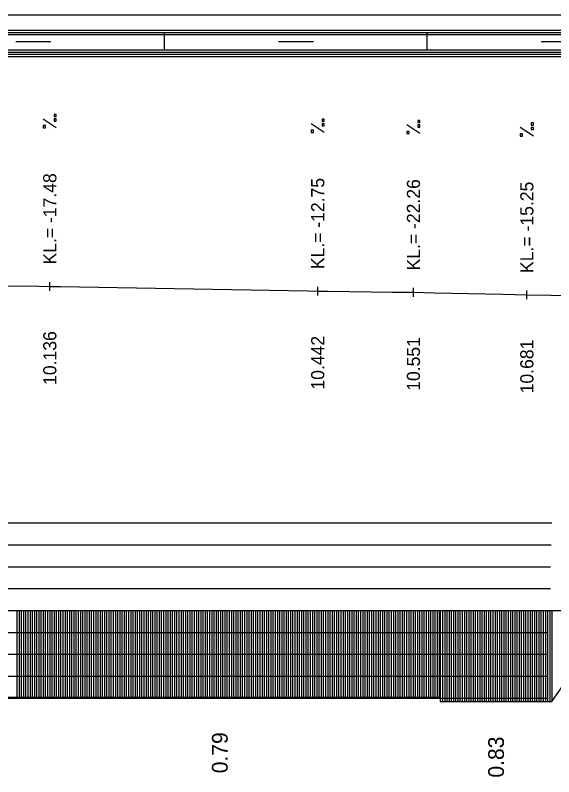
# Model space of a CAD drawing. Extents: x 2 to 10148, y 0 to 380.
# Drawn here: x 1307.9 to 1369.4, y 293 to 380 of the extents above; entities that cross this region are included whole.
import ezdxf

# ---------------------------------------------------------------- set-up
doc = ezdxf.new("R2010")
doc.units = 0
for name, color, linetype in [('NIVELETA_CARA', 7, 'Continuous'), ('NIVELETA_TEXT', 7, 'Continuous'), ('RAM', 7, 'Continuous'), ('ZRYCHL_CARA_C', 7, 'Continuous'), ('ZRYCHL_RASTR', 7, 'Continuous'), ('ZRYCHL_TEXT', 7, 'Continuous')]:
    doc.layers.add(name, color=color, linetype=linetype)

msp = doc.modelspace()

# ---------------------------------------------------------------- linework, layer by layer
at = {"layer": 'NIVELETA_CARA'}
for p, q in [((1306.124, 349.095), (1310.651, 349.038)), ((1310.651, 349.038), (1311.883, 349.022)), ((1311.883, 348.522), (1311.883, 349.522)), ((1311.883, 349.022), (1313.114, 349.001)), ((1313.114, 349.001), (1341.305, 348.508)), ((1342.487, 347.987), (1342.487, 348.987)), ((1353.419, 347.848), (1353.419, 348.848)), ((1341.305, 348.508), (1342.487, 348.487)), ((1342.487, 348.487), (1343.669, 348.472)), ((1343.669, 348.472), (1351.044, 348.378)), ((1351.044, 348.378), (1353.419, 348.348)), ((1353.419, 348.348), (1355.795, 348.295)), ((1355.795, 348.295), (1363.64, 348.12)), ((1363.64, 348.12), (1366.373, 348.06)), ((1366.373, 347.56), (1366.373, 348.56)), ((1366.373, 348.06), (1369.105, 348.018)), ((1369.105, 348.018), (1381.569, 347.828))]:
    msp.add_line(p, q, dxfattribs=at)
at = {"layer": 'NIVELETA_TEXT'}
for p, q in [((1312.63, 367.149), (1311.136, 368.14)), ((1312.631, 368.666), (1312.383, 368.666)), ((1312.383, 368.666), (1312.383, 368.423)), ((1312.383, 368.423), (1312.388, 368.418)), ((1312.383, 368.418), (1312.631, 368.418)), ((1312.631, 368.154), (1312.383, 368.154)), ((1312.383, 368.154), (1312.383, 367.911)), ((1312.631, 368.418), (1312.631, 368.666)), ((1312.631, 367.907), (1312.631, 368.154)), ((1343.235, 368.131), (1342.987, 368.131)), ((1342.987, 368.131), (1342.987, 367.888)), ((1343.235, 367.883), (1343.235, 368.131)), ((1354.167, 367.991), (1353.92, 367.991)), ((1353.92, 367.991), (1353.92, 367.748)), ((1354.167, 367.744), (1354.167, 367.991)), ((1311.383, 367.397), (1311.136, 367.397)), ((1311.136, 367.397), (1311.136, 367.154)), ((1311.136, 367.154), (1311.14, 367.149)), ((1311.136, 367.149), (1311.383, 367.149)), ((1311.383, 367.149), (1311.383, 367.397)), ((1312.383, 367.911), (1312.388, 367.907)), ((1312.383, 367.907), (1312.631, 367.907)), ((1343.234, 366.614), (1341.74, 367.605)), ((1342.987, 367.888), (1342.992, 367.883)), ((1342.987, 367.883), (1343.235, 367.883)), ((1343.235, 367.619), (1342.987, 367.619)), ((1342.987, 367.619), (1342.987, 367.376)), ((1342.987, 367.376), (1342.992, 367.372)), ((1342.987, 367.372), (1343.235, 367.372)), ((1343.235, 367.372), (1343.235, 367.619)), ((1354.166, 366.475), (1352.672, 367.466)), ((1353.92, 367.748), (1353.925, 367.744)), ((1353.92, 367.744), (1354.167, 367.744)), ((1354.167, 367.48), (1353.92, 367.48)), ((1353.92, 367.48), (1353.92, 367.237)), ((1353.92, 367.237), (1353.925, 367.232)), ((1353.92, 367.232), (1354.167, 367.232)), ((1354.167, 367.232), (1354.167, 367.48)), ((1367.119, 366.187), (1365.625, 367.177)), ((1367.12, 367.703), (1366.873, 367.703)), ((1366.873, 367.703), (1366.873, 367.46)), ((1366.873, 367.46), (1366.878, 367.455)), ((1366.873, 367.455), (1367.12, 367.455)), ((1367.12, 367.192), (1366.873, 367.192)), ((1366.873, 367.192), (1366.873, 366.949)), ((1367.12, 367.455), (1367.12, 367.703)), ((1367.12, 366.944), (1367.12, 367.192)), ((1341.987, 366.862), (1341.74, 366.862)), ((1341.74, 366.862), (1341.74, 366.619)), ((1341.74, 366.619), (1341.745, 366.614)), ((1341.74, 366.614), (1341.987, 366.614)), ((1341.987, 366.614), (1341.987, 366.862)), ((1352.92, 366.723), (1352.672, 366.723)), ((1352.672, 366.723), (1352.672, 366.48)), ((1352.672, 366.48), (1352.677, 366.475)), ((1352.672, 366.475), (1352.92, 366.475)), ((1352.92, 366.475), (1352.92, 366.723)), ((1365.873, 366.434), (1365.625, 366.434)), ((1365.625, 366.434), (1365.625, 366.191)), ((1365.873, 366.187), (1365.873, 366.434)), ((1366.873, 366.949), (1366.878, 366.944)), ((1366.873, 366.944), (1367.12, 366.944)), ((1365.625, 366.191), (1365.63, 366.187)), ((1365.625, 366.187), (1365.873, 366.187))]:
    msp.add_line(p, q, dxfattribs=at)
at = {"layer": 'RAM'}
for p, q in [((1850.829, 380), (1245.39, 380)), ((1850.829, 378.25), (1245.39, 378.25)), ((1850.829, 378), (1245.39, 378)), ((1850.829, 377.75), (1245.39, 377.75)), ((1325, 376), (1325, 378)), ((1355, 376), (1355, 378)), ((1308, 377), (1312, 377)), ((1338, 377), (1342, 377)), ((1368, 377), (1372, 377)), ((1850.829, 376), (1245.39, 376)), ((1850.829, 375.75), (1245.39, 375.75)), ((1850.829, 375.5), (1245.39, 375.5)), ((1850.829, 375.25), (1245.39, 375.25))]:
    msp.add_line(p, q, dxfattribs=at)
at = {"layer": 'ZRYCHL_CARA_C'}
for p, q in [((1245.39, 312), (1850.829, 312)), ((1308.124, 312), (1308.124, 302.112)), ((1308.374, 312), (1308.374, 302.112)), ((1308.624, 312), (1308.624, 302.112)), ((1308.874, 312), (1308.874, 302.112)), ((1309.124, 312), (1309.124, 302.112)), ((1309.374, 312), (1309.374, 302.112)), ((1309.624, 312), (1309.624, 302.112)), ((1309.874, 312), (1309.874, 302.112)), ((1310.124, 312), (1310.124, 302.112)), ((1310.374, 312), (1310.374, 302.112)), ((1310.624, 312), (1310.624, 302.112)), ((1310.874, 312), (1310.874, 302.112)), ((1311.124, 312), (1311.124, 302.112)), ((1311.374, 312), (1311.374, 302.112)), ((1311.624, 312), (1311.624, 302.112)), ((1311.874, 312), (1311.874, 302.112)), ((1312.124, 312), (1312.124, 302.112)), ((1312.374, 312), (1312.374, 302.112)), ((1312.624, 312), (1312.624, 302.112)), ((1312.874, 312), (1312.874, 302.112)), ((1313.124, 312), (1313.124, 302.112)), ((1313.374, 312), (1313.374, 302.112)), ((1313.624, 312), (1313.624, 302.112)), ((1313.874, 312), (1313.874, 302.112)), ((1314.124, 312), (1314.124, 302.112)), ((1314.374, 312), (1314.374, 302.112)), ((1314.624, 312), (1314.624, 302.112)), ((1314.874, 312), (1314.874, 302.112)), ((1315.124, 312), (1315.124, 302.112)), ((1315.374, 312), (1315.374, 302.112)), ((1315.624, 312), (1315.624, 302.112)), ((1315.874, 312), (1315.874, 302.112)), ((1316.124, 312), (1316.124, 302.112)), ((1316.374, 312), (1316.374, 302.112)), ((1316.624, 312), (1316.624, 302.112)), ((1316.874, 312), (1316.874, 302.112)), ((1317.124, 312), (1317.124, 302.112)), ((1317.374, 312), (1317.374, 302.112)), ((1317.624, 312), (1317.624, 302.112)), ((1317.874, 312), (1317.874, 302.112)), ((1318.124, 312), (1318.124, 302.112)), ((1318.374, 312), (1318.374, 302.112)), ((1318.624, 312), (1318.624, 302.112)), ((1318.874, 312), (1318.874, 302.112)), ((1319.124, 312), (1319.124, 302.112)), ((1319.374, 312), (1319.374, 302.112)), ((1319.624, 312), (1319.624, 302.112)), ((1319.874, 312), (1319.874, 302.112)), ((1320.124, 312), (1320.124, 302.112)), ((1320.374, 312), (1320.374, 302.112)), ((1320.624, 312), (1320.624, 302.112)), ((1320.874, 312), (1320.874, 302.112)), ((1321.124, 312), (1321.124, 302.112)), ((1321.374, 312), (1321.374, 302.112)), ((1321.624, 312), (1321.624, 302.112)), ((1321.874, 312), (1321.874, 302.112)), ((1322.124, 312), (1322.124, 302.112)), ((1322.374, 312), (1322.374, 302.112)), ((1322.624, 312), (1322.624, 302.112)), ((1322.874, 312), (1322.874, 302.112)), ((1323.124, 312), (1323.124, 302.112)), ((1323.374, 312), (1323.374, 302.112)), ((1323.624, 312), (1323.624, 302.112)), ((1323.874, 312), (1323.874, 302.112)), ((1324.124, 312), (1324.124, 302.112)), ((1324.374, 312), (1324.374, 302.112)), ((1324.624, 312), (1324.624, 302.112)), ((1324.874, 312), (1324.874, 302.112)), ((1325.124, 312), (1325.124, 302.112)), ((1325.374, 312), (1325.374, 302.112)), ((1325.624, 312), (1325.624, 302.112)), ((1325.874, 312), (1325.874, 302.112)), ((1326.124, 312), (1326.124, 302.112)), ((1326.374, 312), (1326.374, 302.112)), ((1326.624, 312), (1326.624, 302.112)), ((1326.874, 312), (1326.874, 302.112)), ((1327.124, 312), (1327.124, 302.112)), ((1327.374, 312), (1327.374, 302.112)), ((1327.624, 312), (1327.624, 302.112)), ((1327.874, 312), (1327.874, 302.112)), ((1328.124, 312), (1328.124, 302.112)), ((1328.374, 312), (1328.374, 302.112)), ((1328.624, 312), (1328.624, 302.112)), ((1328.874, 312), (1328.874, 302.112)), ((1329.124, 312), (1329.124, 302.112)), ((1329.374, 312), (1329.374, 302.112)), ((1329.624, 312), (1329.624, 302.112)), ((1329.874, 312), (1329.874, 302.112)), ((1330.124, 312), (1330.124, 302.112)), ((1330.374, 312), (1330.374, 302.112)), ((1330.624, 312), (1330.624, 302.112)), ((1330.874, 312), (1330.874, 302.112)), ((1331.124, 312), (1331.124, 302.112)), ((1331.374, 312), (1331.374, 302.112)), ((1331.624, 312), (1331.624, 302.112)), ((1331.874, 312), (1331.874, 302.112)), ((1332.124, 312), (1332.124, 302.112)), ((1332.374, 312), (1332.374, 302.112)), ((1332.624, 312), (1332.624, 302.112)), ((1332.874, 312), (1332.874, 302.112)), ((1333.124, 312), (1333.124, 302.112)), ((1333.374, 312), (1333.374, 302.112)), ((1333.624, 312), (1333.624, 302.112)), ((1333.874, 312), (1333.874, 302.112)), ((1334.124, 312), (1334.124, 302.112)), ((1334.374, 312), (1334.374, 302.112)), ((1334.624, 312), (1334.624, 302.112)), ((1334.874, 312), (1334.874, 302.112)), ((1335.124, 312), (1335.124, 302.112)), ((1335.374, 312), (1335.374, 302.112)), ((1335.624, 312), (1335.624, 302.112)), ((1335.874, 312), (1335.874, 302.112)), ((1336.124, 312), (1336.124, 302.112)), ((1336.374, 312), (1336.374, 302.112)), ((1336.624, 312), (1336.624, 302.112)), ((1336.874, 312), (1336.874, 302.112)), ((1337.124, 312), (1337.124, 302.112)), ((1337.374, 312), (1337.374, 302.112)), ((1337.624, 312), (1337.624, 302.112)), ((1337.874, 312), (1337.874, 302.112)), ((1338.124, 312), (1338.124, 302.112)), ((1338.374, 312), (1338.374, 302.112)), ((1338.624, 312), (1338.624, 302.112)), ((1338.874, 312), (1338.874, 302.112)), ((1339.124, 312), (1339.124, 302.112)), ((1339.374, 312), (1339.374, 302.112)), ((1339.624, 312), (1339.624, 302.112)), ((1339.874, 312), (1339.874, 302.112)), ((1340.124, 312), (1340.124, 302.112)), ((1340.374, 312), (1340.374, 302.112)), ((1340.624, 312), (1340.624, 302.112)), ((1340.874, 312), (1340.874, 302.112)), ((1341.124, 312), (1341.124, 302.112)), ((1341.374, 312), (1341.374, 302.112)), ((1341.624, 312), (1341.624, 302.112)), ((1341.874, 312), (1341.874, 302.112)), ((1342.124, 312), (1342.124, 302.112)), ((1342.374, 312), (1342.374, 302.112)), ((1342.624, 312), (1342.624, 302.112)), ((1342.874, 312), (1342.874, 302.112)), ((1343.124, 312), (1343.124, 302.112)), ((1343.374, 312), (1343.374, 302.112)), ((1343.624, 312), (1343.624, 302.112)), ((1343.874, 312), (1343.874, 302.112)), ((1344.124, 312), (1344.124, 302.112)), ((1344.374, 312), (1344.374, 302.112)), ((1344.624, 312), (1344.624, 302.112)), ((1344.874, 312), (1344.874, 302.112)), ((1345.124, 312), (1345.124, 302.112)), ((1345.374, 312), (1345.374, 302.112)), ((1345.624, 312), (1345.624, 302.112)), ((1345.874, 312), (1345.874, 302.112)), ((1346.124, 312), (1346.124, 302.112)), ((1346.374, 312), (1346.374, 302.112)), ((1346.624, 312), (1346.624, 302.112)), ((1346.874, 312), (1346.874, 302.112)), ((1347.124, 312), (1347.124, 302.112)), ((1347.374, 312), (1347.374, 302.112)), ((1347.624, 312), (1347.624, 302.112)), ((1347.874, 312), (1347.874, 302.112)), ((1348.124, 312), (1348.124, 302.112)), ((1348.374, 312), (1348.374, 302.112)), ((1348.624, 312), (1348.624, 302.112)), ((1348.874, 312), (1348.874, 302.112)), ((1349.124, 312), (1349.124, 302.112)), ((1349.374, 312), (1349.374, 302.112)), ((1349.624, 312), (1349.624, 302.112)), ((1349.874, 312), (1349.874, 302.112)), ((1350.124, 312), (1350.124, 302.112)), ((1350.374, 312), (1350.374, 302.112)), ((1350.624, 312), (1350.624, 302.112)), ((1350.874, 312), (1350.874, 302.112)), ((1351.124, 312), (1351.124, 302.112)), ((1351.374, 312), (1351.374, 302.112)), ((1351.624, 312), (1351.624, 302.112)), ((1351.874, 312), (1351.874, 302.112)), ((1352.124, 312), (1352.124, 302.112)), ((1352.374, 312), (1352.374, 302.112)), ((1352.624, 312), (1352.624, 302.112)), ((1352.874, 312), (1352.874, 302.112)), ((1353.124, 312), (1353.124, 302.112)), ((1353.374, 312), (1353.374, 302.112)), ((1353.624, 312), (1353.624, 302.112)), ((1353.874, 312), (1353.874, 302.112)), ((1354.124, 312), (1354.124, 302.112)), ((1354.374, 312), (1354.374, 302.112)), ((1354.624, 312), (1354.624, 302.112)), ((1354.874, 312), (1354.874, 302.112)), ((1355.124, 312), (1355.124, 302.112)), ((1355.374, 312), (1355.374, 302.112)), ((1355.624, 312), (1355.624, 302.112)), ((1355.874, 312), (1355.874, 302.112)), ((1356.124, 312), (1356.124, 302.112)), ((1356.374, 312), (1356.374, 302.112)), ((1356.486, 312), (1356.486, 301.618)), ((1356.736, 312), (1356.736, 301.618)), ((1356.986, 312), (1356.986, 301.618)), ((1357.236, 312), (1357.236, 301.618)), ((1357.486, 312), (1357.486, 301.618)), ((1357.736, 312), (1357.736, 301.618)), ((1357.986, 312), (1357.986, 301.618)), ((1358.236, 312), (1358.236, 301.618)), ((1358.486, 312), (1358.486, 301.618)), ((1358.736, 312), (1358.736, 301.618)), ((1358.986, 312), (1358.986, 301.618)), ((1359.236, 312), (1359.236, 301.618)), ((1359.486, 312), (1359.486, 301.618)), ((1359.736, 312), (1359.736, 301.618)), ((1359.986, 312), (1359.986, 301.618)), ((1360.236, 312), (1360.236, 301.618)), ((1360.486, 312), (1360.486, 301.618)), ((1360.736, 312), (1360.736, 301.618)), ((1360.986, 312), (1360.986, 301.618)), ((1361.236, 312), (1361.236, 301.618)), ((1361.486, 312), (1361.486, 301.618)), ((1361.736, 312), (1361.736, 301.618)), ((1361.986, 312), (1361.986, 301.618)), ((1362.236, 312), (1362.236, 301.618)), ((1362.486, 312), (1362.486, 301.618)), ((1362.736, 312), (1362.736, 301.618)), ((1362.986, 312), (1362.986, 301.618)), ((1363.236, 312), (1363.236, 301.618)), ((1363.486, 312), (1363.486, 301.618)), ((1363.736, 312), (1363.736, 301.618)), ((1363.986, 312), (1363.986, 301.618)), ((1364.236, 312), (1364.236, 301.618)), ((1364.486, 312), (1364.486, 301.618)), ((1364.736, 312), (1364.736, 301.618)), ((1364.986, 312), (1364.986, 301.618)), ((1365.236, 312), (1365.236, 301.618)), ((1365.486, 312), (1365.486, 301.618)), ((1365.736, 312), (1365.736, 301.618)), ((1365.986, 312), (1365.986, 301.618)), ((1366.236, 312), (1366.236, 301.618)), ((1366.486, 312), (1366.486, 301.618)), ((1366.736, 312), (1366.736, 301.618)), ((1366.986, 312), (1366.986, 301.618)), ((1367.236, 312), (1367.236, 301.618)), ((1367.486, 312), (1367.486, 301.618)), ((1367.736, 312), (1367.736, 301.618)), ((1367.986, 312), (1367.986, 301.618)), ((1368.236, 312), (1368.236, 301.618)), ((1368.486, 312), (1368.486, 301.618)), ((1368.736, 312), (1368.736, 301.618)), ((1368.986, 312), (1368.986, 301.618)), ((1369.226, 312), (1369.226, 301.618)), ((1369.226, 301.618), (1376.436, 312)), ((1306.124, 302.112), (1356.486, 302.112)), ((1356.486, 302.112), (1356.486, 301.618)), ((1356.486, 301.618), (1369.226, 301.618))]:
    msp.add_line(p, q, dxfattribs=at)
at = {"layer": 'ZRYCHL_RASTR'}
for p, q in [((1245.39, 322), (1369.208, 322)), ((1245.39, 319.5), (1369.158, 319.5)), ((1245.39, 317), (1369.083, 317)), ((1245.39, 314.5), (1369.083, 314.5)), ((1245.39, 309.5), (1368.813, 309.5)), ((1245.39, 307), (1368.776, 307)), ((1245.39, 304.5), (1368.79, 304.5)), ((1245.39, 302), (1368.804, 302))]:
    msp.add_line(p, q, dxfattribs=at)

# ---------------------------------------------------------------- texts
at = {"layer": 'NIVELETA_TEXT'}
for s, p in [('KL.= -17.48', (1312.633, 351.522)), ('KL.= -12.75', (1343.237, 350.987)), ('KL.= -22.26', (1354.169, 350.848)), ('KL.= -15.25', (1367.122, 350.56)), ('10.136', (1312.633, 337.772)), ('10.442', (1343.237, 337.237)), ('10.551', (1354.169, 337.098)), ('10.681', (1367.122, 336.81))]:
    msp.add_text(s, height=1.5, rotation=90, dxfattribs=at).set_placement(p)
at = {"layer": 'ZRYCHL_TEXT'}
for s, p in [('0.79', (1332.205, 293.413)), ('0.83', (1363.756, 292.918))]:
    msp.add_text(s, height=1.8, rotation=90, dxfattribs=at).set_placement(p)

doc.saveas('drawing.dxf')
